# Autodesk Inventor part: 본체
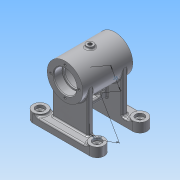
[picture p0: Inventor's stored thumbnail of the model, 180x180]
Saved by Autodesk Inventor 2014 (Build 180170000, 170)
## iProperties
Created: 2015-11
Part Number: 본체
Material: 알루미늄 6061
Document SubType Name: Modeling
Designer: 103-07
Density: 2.71 g/cm^3
Appearance: 알루미늄 - 평지
Mass: 359.155 g
Surface Area: 459.458 cm^2
Volume: 132.529 cm^3
Author: 103-07
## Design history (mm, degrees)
sketch "스케치1"
  geometry: L1 (-40, 40)-(40, 40); L2 (-40, 20)-(40, 20); L3 (-40, -20)-(40, -20); L4 (-40, -40)-(40, -40); A1 r 10 centre (-40, 30) between (-40, 40) and (-40, 20); A2 r 10 centre (40, 30) between (40, 40) and (40, 20); A3 r 10 centre (-40, -30) between (-40, -20) and (-40, -40); A4 r 10 centre (40, -30) between (40, -20) and (40, -40); 3 further points
  constraints: 8 end point, 8 point on circle, 7 tangent, 4 centre point, 3 equal radius, 2 horizontal, 2 midpoint, 2 vertical alignment, 1 horizontal alignment, 1 parallel
  dimensions: "d0" = 20 diameter of A1; "d1" = 80 distance of A2.centre A1.centre; "d2" = 80 distance between parallel lines of L4 L1; "d3" = 40 distance from line of L4 point (0, 0)
extrude "돌출1" new body sketch "스케치1" distance "d4" = 10; taper "d5" = 0 deg
extrude "돌출2" join sketch "스케치1" distance "d6" = 13; taper "d7" = 0 deg
node "작업 평면1"
sketch "스케치2"
  geometry: L1 (-35, 68)-(35, 68); L2 (-20, 0)-(-40, 0) reference; L3 (-35, 68)-(-35, 93); L4 (-35, 93)-(35, 93); L5 (35, 93)-(35, 68); 2 further points
  constraints: 8 end point, 2 perpendicular, 1 horizontal, 1 midpoint, 1 parallel, 1 vertical alignment
  dimensions: "d9" = 70 distance of L1.start L1.end; "d10" = 68 distance between parallel lines of L2 L1; "d11" = 50 diameter of L4 L1
revolve "회전1" sketch "스케치2" stored, may be unused: angle "d12" = 90 deg
sketch "스케치5"
  geometry: L1 (0, 10)-(80, 10) reference; L2 (15, 68)-(15, 10); L3 (65, 68)-(65, 10); L4 (15, 68)-(65, 68); A1 r 25 centre (40, 68) between (15, 68) and (65, 68) reference; 1 further point
  constraints: 6 end point, 3 perpendicular, 2 point on circle, 2 point on line, 2 tangent
extrude "돌출3" join sketch "스케치5" distance "d15" = 8; taper "d16" = 0 deg
node "작업 평면5"
sketch "스케치7"
  geometry: L1 (-25, 20)-(25, 20) reference; L2 (25, -20)-(-25, -20) reference; L3 (-25, -28)-(25, -28) reference; L4 (25, 28)-(-25, 28) reference; L5 (-4, 28)-(4, 28); L6 (4, 28)-(4, -28); L7 (4, -28)-(-4, -28); L8 (-4, -28)-(-4, 28); L9 (-4, 28)-(4, -28); L10 (4, 28)-(-4, -28); 1 further point
  constraints: 12 end point, 2 midpoint, 2 parallel, 1 horizontal, 1 perpendicular, 1 point on line
  dimensions: "d23" = 8 distance of L5.start L5.end
extrude "돌출4" join sketch "스케치7" stored distance "d24" = 8; taper "d25" = 0 deg
sketch "스케치8"
  geometry: L1 (0, 40)-(0, 0) reference; L2 (13.5, 28)-(13.5, 12); L3 (6.5, 12)-(6.5, 28); L4 (-23, -20)-(-23, 0) reference; A1 r 3.5 centre (10, 12) between (6.5, 12) and (13.5, 12); A2 r 3.5 centre (10, 28) between (13.5, 28) and (6.5, 28); 3 further points
  constraints: 4 end point, 4 point on circle, 4 tangent, 2 centre point, 2 midpoint, 2 parallel, 1 horizontal alignment
  dimensions: "d26" = 23 dimension on A1 A2; "d27" = 33 distance from line of L4 A1.centre; "d28" = 3.5 radius of A1
extrude "돌출5" cut sketch "스케치8" stored distance "d29" = 0; taper "d30" = 0 deg
node "작업 평면6"
sketch "스케치9"
  geometry: C1 r 5 at (0, 0); 1 further point
  constraints: 1 centre point, 1 coincident
  dimensions: "d32" = 10 diameter of C1
extrude "돌출6" join sketch "스케치9" stored distance "d33" = 8; taper "d34" = 0 deg
node "작업 평면7"
sketch "스케치10"
  geometry: L1 (-35, 43)-(-35, 93) reference; L2 (35, 43)-(35, 93) reference; L3 (-35, 68)-(35, 68); L4 (-35, 68)-(-35, 84); L5 (-35, 84)-(-23, 84); L6 (-23, 84)-(-23, 82); L7 (-23, 82)-(-21, 82); L8 (-21, 82)-(-21, 89); L9 (-21, 89)-(21, 89); L10 (21, 89)-(21, 82); L11 (21, 82)-(23, 82); L12 (23, 82)-(23, 84); L13 (23, 84)-(35, 84); L14 (35, 84)-(35, 68); 1 further point
  constraints: 24 end point, 6 parallel, 3 perpendicular, 2 midpoint, 2 point on line, 1 collinear
  dimensions: "d36" = 32 diameter of L5 L3; "d37" = 28 diameter of L7 L3; "d38" = 42 diameter of L9 L3; "d39" = 28 diameter of L11 L3; "d40" = 32 diameter of L13 L3; "d41" = 12 distance of L4.end L5.end; "d42" = 12 distance of L12.end L13.end; "d43" = 42 distance of L8.end L9.end; "d44" = 2 distance of L6.end L7.end
revolve "회전2" sketch "스케치10" stored, may be unused: angle "d45" = 90 deg
hole "구멍1" diameter "d48" = 6; stored, may be unused: countersink angle "d52" = 90 deg, drill point angle "d54" = 118 deg; dims "d46" = 10, "d47" = 10, "d49" = 6, "d50" = 12, "d51" = 4, "d53" = 8
hole "구멍2" diameter "d57" = 6; stored, may be unused: countersink angle "d61" = 90 deg, drill point angle "d63" = 118 deg; dims "d55" = 10, "d56" = 10, "d58" = 6, "d59" = 12, "d60" = 4, "d62" = 8
hole "구멍3" diameter "d66" = 6; stored, may be unused: countersink angle "d70" = 90 deg, drill point angle "d72" = 118 deg; dims "d64" = 10, "d65" = 10, "d67" = 6, "d68" = 12, "d69" = 4, "d71" = 8
hole "구멍4" diameter "d75" = 6; stored, may be unused: countersink angle "d79" = 90 deg, drill point angle "d81" = 118 deg; dims "d73" = 10, "d74" = 10, "d76" = 6, "d77" = 12, "d78" = 4, "d80" = 8
sketch "스케치12"
  geometry: C1 r 16 at (0, 0) reference; C2 r 25 at (0, 0) reference; A1 r 20 centre (0, 0) between (0, 20) and (0, -20); 3 further points
  constraints: 4 point on circle, 2 horizontal alignment, 2 vertical alignment, 1 centre point, 1 coincident
  dimensions: "d83" = 40 diameter of A1
hole "구멍5" sketch "스케치12" at (0, 20), (0, -20), (20, 0), (-20, 0) diameter "d84" = 3.242; stored, may be unused: countersink angle "d88" = 90 deg, drill point angle "d90" = 118 deg; dims "d85" = 8, "d86" = 12, "d87" = 4, "d89" = 10
node "작업 평면8"
sketch "스케치13"
  geometry: L1 (-35, 25)-(-35, -25) reference; L2 (35, 25)-(-35, 25) reference; 2 further points
  constraints: 1 other
  dimensions: "d91" = 35 distance from line of point (0, 0) L1; "d92" = 25 distance from line of L2 point (0, 0)
feature "엠보싱1" sketch "스케치13" dims "d9" = 70, "d10" = 68, "d11" = 50, "d93" = 0.5, "d94" = 0
node "작업 평면9"
sketch "스케치14"
  geometry: L1 (0, 68)-(14, 43.751); C1 r 14 at (0, 68) reference; 1 further point
  constraints: 2 end point
  dimensions: "d96" = 30 deg dimension on L1.start point (0, 0) L1.end; "d97" = 28 distance of L1.start L1.end
node "작업 평면10"
hole "구멍7" diameter "d112" = 5.188; stored, may be unused: countersink angle "d116" = 90 deg, drill point angle "d118" = 0 deg; dims "d110" = 10, "d111" = 10, "d113" = 8, "d114" = 12, "d115" = 4, "d117" = 10
chamfer "모따기1" distance "d119" = 1; stored, may be unused: second distance "d120" = 2, angle "d121" = 45 deg
fillet "모깎기1" dims "d122" = 0.3, "d123" = 3, "d124" = 2
fillet "모깎기3" dims "d126" = 2
node "작업 평면11"
sketch "스케치16"
  geometry: L1 (0, 68)-(-14, 43.751); C1 r 14 at (0, 68) reference; 1 further point
  constraints: 2 end point
  dimensions: "d128" = 30 deg dimension on L1.start point (0, 0) L1.end; "d129" = 28 distance of L1.start L1.end
node "작업 평면12"
sketch "스케치17"
  geometry: C1 r 6 at (0, 0); 2 further points
  constraints: 1 centre point, 1 coincident
  dimensions: "d130" = 12 diameter of C1
extrude "돌출8" join sketch "스케치17" stored distance "d131" = 0; taper "d132" = 0 deg
hole "구멍8" diameter "d135" = 5.188; stored, may be unused: countersink angle "d139" = 90 deg, drill point angle "d141" = 0 deg; dims "d133" = 10, "d134" = 10, "d136" = 6, "d137" = 4, "d138" = 2, "d140" = 8
fillet "모깎기4" dims "d142" = 2
node "솔리드1"
mirror "대칭1"
mirror "대칭2"
node "투영된 루프2"
other parameters: "d8" = 0, "d22" = -23, "d31" = 96, "d35" = 0, "d95" = 0, "d127" = 0
